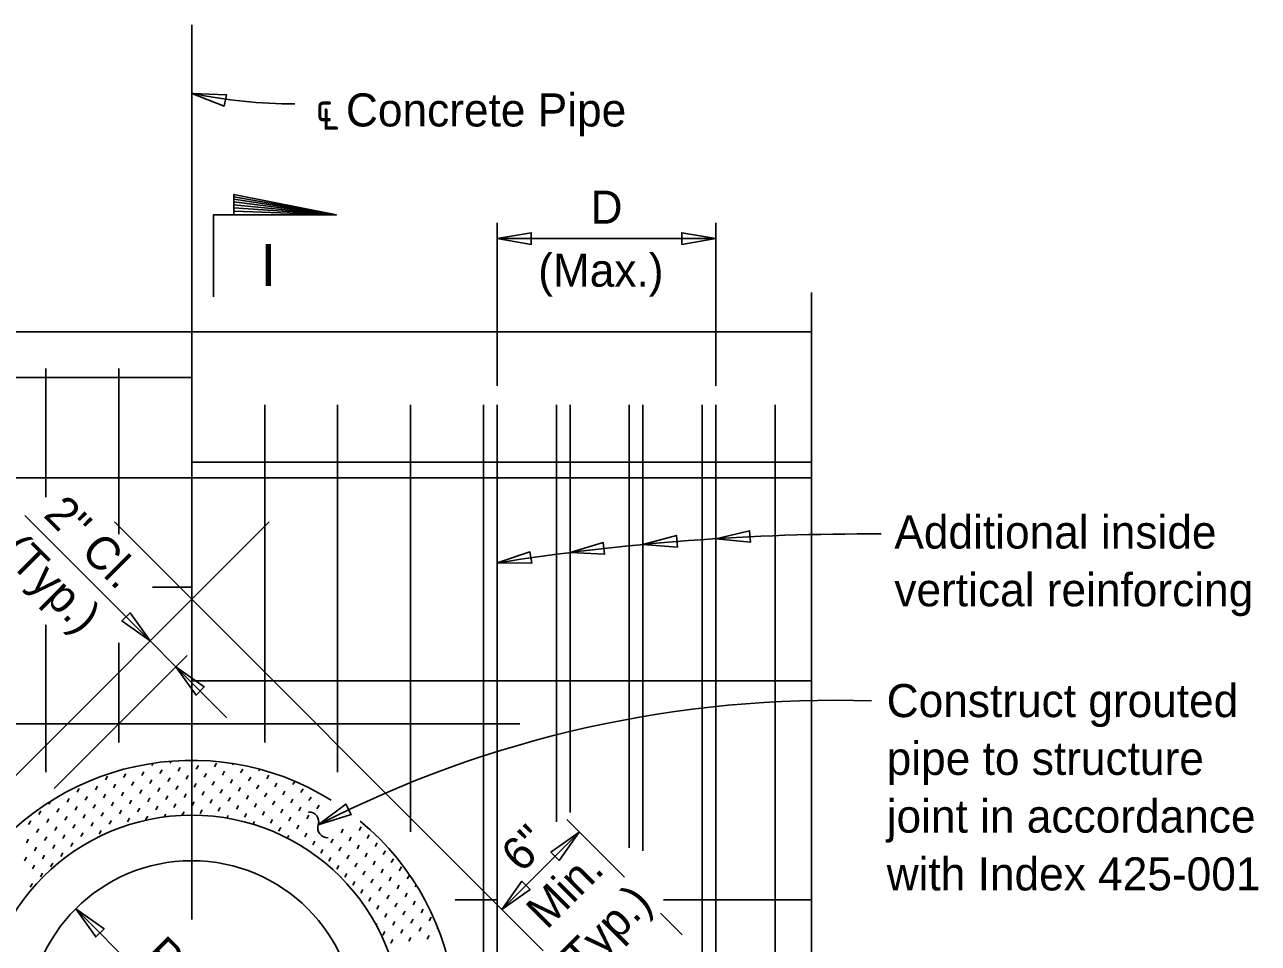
# Model space of a CAD drawing. Extents: x 10605.2 to 10672.7, y 76423.8 to 76450.2.
# Drawn here: x 10643.8 to 10649.44, y 76434.62 to 76438.82 of the extents above; entities that cross this region are included whole.
import ezdxf

# ---------------------------------------------------------------- set-up
doc = ezdxf.new("R2010")
doc.units = 0
for name, color, linetype in [('AdhocPoint_dp', 7, 'Continuous'), ('Border', 7, 'Continuous'), ('Patterning', 7, 'Continuous'), ('PlotBorder_dp', 7, 'Continuous'), ('SheetBorder_dp', 7, 'Continuous'), ('SheetLines_dp', 7, 'Continuous'), ('TextMisc', 7, 'Continuous')]:
    doc.layers.add(name, color=color, linetype=linetype)

msp = doc.modelspace()

# ---------------------------------------------------------------- linework, layer by layer
at = {"layer": 'AdhocPoint_dp'}
for p, q in [((10645.2285, 76437.947), (10644.7597, 76438.0295)), ((10644.7597, 76438.0195), (10645.2285, 76437.947)), ((10645.2285, 76437.947), (10644.7597, 76438.007)), ((10644.7597, 76437.9932), (10645.2285, 76437.947)), ((10645.2285, 76437.947), (10644.7597, 76437.9795)), ((10644.7597, 76437.9645), (10645.2285, 76437.947)), ((10645.9629, 76437.1656), (10645.9629, 76437.9115)), ((10646.9628, 76437.1656), (10646.9628, 76437.9115)), ((10645.9629, 76437.8391), (10646.9628, 76437.8391)), ((10643.8042, 76436.5724), (10644.3769, 76435.9996)), ((10644.4948, 76435.8818), (10644.3769, 76435.9996)), ((10643.9382, 76435.3252), (10644.5463, 76435.9333)), ((10644.4948, 76435.8818), (10644.7281, 76435.6485)), ((10646.5446, 76434.9197), (10646.2811, 76435.1831)), ((10646.3381, 76435.1261), (10645.9846, 76434.7726)), ((10645.0945, 76433.7181), (10644.0369, 76434.7757)), ((10646.8084, 76434.6559), (10646.7092, 76434.7551))]:
    msp.add_line(p, q, dxfattribs=at)
for points in [[(10644.5672, 76438.5028), (10644.7146, 76438.4448), (10644.7255, 76438.4966)], [(10645.963, 76437.8391), (10646.1191, 76437.8126), (10646.1191, 76437.8655)], [(10646.9629, 76437.8391), (10646.8067, 76437.8655), (10646.8067, 76437.8126)], [(10646.6295, 76436.4407), (10646.7825, 76436.4818), (10646.7875, 76436.4291)], [(10646.9629, 76436.4671), (10647.117, 76436.5035), (10647.1204, 76436.4507)], [(10646.2962, 76436.4038), (10646.4479, 76436.4496), (10646.4545, 76436.3971)], [(10645.963, 76436.3564), (10646.1131, 76436.4069), (10646.1214, 76436.3547)], [(10644.377, 76435.9996), (10644.2852, 76436.1288), (10644.2478, 76436.0914)], [(10644.4948, 76435.8818), (10644.5866, 76435.7526), (10644.624, 76435.79)], [(10645.1449, 76435.1594), (10645.296, 76435.2071), (10645.2719, 76435.2542)], [(10646.3382, 76435.1261), (10646.209, 76435.0344), (10646.2464, 76434.9969)], [(10645.9846, 76434.7726), (10646.1137, 76434.8643), (10646.0763, 76434.9017)], [(10644.0369, 76434.7757), (10644.1286, 76434.6466), (10644.1661, 76434.684)]]:
    msp.add_lwpolyline(points, close=True, dxfattribs=at)
for points in [[(10644.666, 76437.572), (10644.666, 76437.947), (10645.2285, 76437.947), (10644.7597, 76438.0407), (10644.7597, 76437.947)], [(10647.4003, 76430.898), (10647.4003, 76434.2116), (10647.3228, 76434.2116), (10647.4003, 76434.2454), (10647.4778, 76434.2791), (10647.4003, 76434.2791), (10647.4003, 76437.5929)]]:
    msp.add_lwpolyline(points, dxfattribs=at)
for centre, radius, start, end in [((10645.0309, 76440.7115), 2.2568, 258.1436, 270.1956), ((10647.6504, 76425.6856), 10.8034, 89.64038, 98.98612), ((10647.5038, 76430.5561), 5.1725, 88.1103, 117.1325), ((10645.1029, 76435.1732), 0.0447, 341.3118, 93.039), ((10645.1876, 76435.1446), 0.0447, 161.3118, 273.039)]:
    msp.add_arc(centre, radius, start, end, dxfattribs=at)
at = {"layer": 'Border'}
msp.add_line((10644.5672, 76438.8167), (10644.5672, 76434.7265), dxfattribs=at)
at = {"layer": 'Patterning'}
for p, q in [((10641.7341, 76437.2036), (10644.5672, 76437.2036)), ((10643.9006, 76437.2453), (10643.9006, 76436.657)), ((10644.2339, 76437.2453), (10644.2339, 76436.4885)), ((10644.5672, 76437.2453), (10644.5672, 76435.9075)), ((10644.9005, 76437.0787), (10644.9005, 76435.5363)), ((10645.2338, 76437.0787), (10645.2338, 76435.4)), ((10645.5671, 76437.0787), (10645.5671, 76435.1272)), ((10645.9004, 76437.0787), (10645.9004, 76431.4121)), ((10645.9629, 76437.0787), (10645.9629, 76431.4121)), ((10646.2337, 76437.0787), (10646.2337, 76435.1732)), ((10646.2962, 76437.0787), (10646.2962, 76435.2162)), ((10646.567, 76437.0787), (10646.567, 76435.0538)), ((10646.6295, 76437.0787), (10646.6295, 76435.0398)), ((10646.9003, 76437.0787), (10646.9003, 76431.4121)), ((10646.9628, 76437.0787), (10646.9628, 76431.4121)), ((10647.2336, 76437.0787), (10647.2336, 76431.4121)), ((10644.5672, 76436.817), (10647.4003, 76436.817)), ((10644.9208, 76436.5435), (10642.2691, 76433.8918)), ((10644.2137, 76436.5435), (10646.1735, 76434.5837)), ((10644.3874, 76436.2453), (10644.5672, 76436.2453)), ((10643.9006, 76436.0738), (10643.9006, 76435.4)), ((10644.2339, 76435.9918), (10644.2339, 76435.5363)), ((10644.5672, 76435.817), (10647.4003, 76435.817)), ((10644.5672, 76435.7102), (10644.5672, 76435.5786)), ((10643.0672, 76435.6204), (10646.0672, 76435.6204)), ((10645.7717, 76434.817), (10645.9629, 76434.817)), ((10646.7228, 76434.817), (10647.4003, 76434.817))]:
    msp.add_line(p, q, dxfattribs=at)
at = {"layer": 'PlotBorder_dp'}
msp.add_line((10641.7341, 76437.412), (10647.4003, 76437.412), dxfattribs=at)
msp.add_circle((10644.5672, 76434.2454), 0.75, dxfattribs=at)
msp.add_arc((10644.5672, 76434.2454), 1.2083, 58.2129, 50.3979, dxfattribs=at)
at = {"layer": 'SheetLines_dp'}
for p, q in [((10644.5512, 76435.4505), (10644.553, 76435.4536)), ((10644.3023, 76435.4214), (10644.3041, 76435.4246)), ((10644.3389, 76435.3847), (10644.3486, 76435.4015)), ((10644.3852, 76435.4311), (10644.3907, 76435.4406)), ((10644.4219, 76435.3945), (10644.4316, 76435.4113)), ((10644.4682, 76435.4408), (10644.4735, 76435.4499)), ((10644.5049, 76435.4042), (10644.5146, 76435.421)), ((10644.5878, 76435.4139), (10644.5976, 76435.4307)), ((10644.6708, 76435.4236), (10644.6805, 76435.4404)), ((10644.7074, 76435.387), (10644.7172, 76435.4038)), ((10644.7538, 76435.4333), (10644.7569, 76435.4386)), ((10644.7904, 76435.3967), (10644.8001, 76435.4135)), ((10644.8734, 76435.4064), (10644.8773, 76435.4131)), ((10644.1729, 76435.3653), (10644.1827, 76435.3821)), ((10644.2096, 76435.3287), (10644.2193, 76435.3455)), ((10644.2559, 76435.375), (10644.2656, 76435.3918)), ((10644.2925, 76435.3384), (10644.3023, 76435.3552)), ((10644.3755, 76435.3481), (10644.3852, 76435.3649)), ((10644.4585, 76435.3578), (10644.4682, 76435.3746)), ((10644.4951, 76435.3212), (10644.5049, 76435.338)), ((10644.5415, 76435.3676), (10644.5512, 76435.3843)), ((10644.5781, 76435.3309), (10644.5878, 76435.3477)), ((10644.6245, 76435.3773), (10644.6342, 76435.3941)), ((10644.6611, 76435.3406), (10644.6708, 76435.3574)), ((10644.7441, 76435.3504), (10644.7538, 76435.3672)), ((10644.827, 76435.3601), (10644.8368, 76435.3769)), ((10644.8637, 76435.3235), (10644.8734, 76435.3403)), ((10644.91, 76435.3698), (10644.9197, 76435.3866)), ((10644.9467, 76435.3332), (10644.9564, 76435.35)), ((10645.0296, 76435.3429), (10645.0383, 76435.3579)), ((10644.0436, 76435.3092), (10644.0533, 76435.326)), ((10644.0802, 76435.2726), (10644.09, 76435.2894)), ((10644.1266, 76435.3189), (10644.1363, 76435.3357)), ((10644.1632, 76435.2823), (10644.1729, 76435.2991)), ((10644.2462, 76435.292), (10644.2559, 76435.3088)), ((10644.3292, 76435.3018), (10644.3389, 76435.3186)), ((10644.3658, 76435.2651), (10644.3755, 76435.2819)), ((10644.4121, 76435.3115), (10644.4219, 76435.3283)), ((10644.4488, 76435.2749), (10644.4585, 76435.2916)), ((10644.5318, 76435.2846), (10644.5415, 76435.3014)), ((10644.6147, 76435.2943), (10644.6245, 76435.3111)), ((10644.6977, 76435.304), (10644.7074, 76435.3208)), ((10644.7343, 76435.2674), (10644.7441, 76435.2842)), ((10644.7807, 76435.3137), (10644.7904, 76435.3305)), ((10644.8173, 76435.2771), (10644.827, 76435.2939)), ((10644.9003, 76435.2868), (10644.91, 76435.3036)), ((10644.9833, 76435.2966), (10644.993, 76435.3134)), ((10645.0663, 76435.3063), (10645.076, 76435.3231)), ((10645.1029, 76435.2697), (10645.1126, 76435.2864)), ((10645.1859, 76435.2794), (10645.1875, 76435.2822)), ((10643.9143, 76435.2531), (10643.9223, 76435.267)), ((10643.9509, 76435.2165), (10643.9606, 76435.2333)), ((10643.9973, 76435.2629), (10644.007, 76435.2797)), ((10644.0339, 76435.2262), (10644.0436, 76435.243)), ((10644.1169, 76435.236), (10644.1266, 76435.2528)), ((10644.1998, 76435.2457), (10644.2096, 76435.2625)), ((10644.2365, 76435.2091), (10644.2462, 76435.2258)), ((10644.2828, 76435.2554), (10644.2925, 76435.2722)), ((10644.3194, 76435.2188), (10644.3292, 76435.2356)), ((10644.4024, 76435.2285), (10644.4121, 76435.2453)), ((10644.4854, 76435.2382), (10644.4951, 76435.255)), ((10644.5684, 76435.2479), (10644.5781, 76435.2647)), ((10644.605, 76435.2113), (10644.6147, 76435.2281)), ((10644.6514, 76435.2577), (10644.6611, 76435.2745)), ((10644.688, 76435.221), (10644.6977, 76435.2378)), ((10644.771, 76435.2308), (10644.7807, 76435.2476)), ((10644.8539, 76435.2405), (10644.8637, 76435.2573)), ((10644.9369, 76435.2502), (10644.9467, 76435.267)), ((10644.9736, 76435.2136), (10644.9833, 76435.2304)), ((10645.0199, 76435.2599), (10645.0296, 76435.2767)), ((10645.0565, 76435.2233), (10645.0663, 76435.2401)), ((10645.1395, 76435.233), (10645.1492, 76435.2498)), ((10643.8216, 76435.1604), (10643.8313, 76435.1772)), ((10643.8679, 76435.2068), (10643.8776, 76435.2236)), ((10643.9046, 76435.1702), (10643.9143, 76435.187)), ((10643.9875, 76435.1799), (10643.9973, 76435.1967)), ((10644.0705, 76435.1896), (10644.0802, 76435.2064)), ((10644.1071, 76435.153), (10644.1169, 76435.1698)), ((10644.1535, 76435.1993), (10644.1632, 76435.2161)), ((10644.1901, 76435.1627), (10644.1998, 76435.1795)), ((10644.2731, 76435.1724), (10644.2828, 76435.1892)), ((10644.3561, 76435.1821), (10644.3658, 76435.1989)), ((10644.4404, 76435.1942), (10644.4488, 76435.2087)), ((10644.522, 76435.2016), (10644.5318, 76435.2184)), ((10644.7273, 76435.189), (10644.7343, 76435.2012)), ((10644.8076, 76435.1941), (10644.8173, 76435.2109)), ((10644.8464, 76435.1613), (10644.8539, 76435.1743)), ((10644.8906, 76435.2039), (10644.9003, 76435.2207)), ((10644.9272, 76435.1672), (10644.9369, 76435.184)), ((10645.0102, 76435.177), (10645.0199, 76435.1937)), ((10645.0932, 76435.1867), (10645.1029, 76435.2035)), ((10643.8582, 76435.1238), (10643.8679, 76435.1406)), ((10643.9412, 76435.1335), (10643.9509, 76435.1503)), ((10643.9778, 76435.0969), (10643.9875, 76435.1137)), ((10644.0242, 76435.1433), (10644.0339, 76435.1601)), ((10644.0608, 76435.1066), (10644.0705, 76435.1234)), ((10644.1438, 76435.1164), (10644.1535, 76435.1331)), ((10644.9638, 76435.1306), (10644.9736, 76435.1474)), ((10645.0468, 76435.1403), (10645.0565, 76435.1571)), ((10645.0834, 76435.1037), (10645.0932, 76435.1205)), ((10645.2494, 76435.1231), (10645.2591, 76435.1399)), ((10645.3324, 76435.1329), (10645.3421, 76435.1497)), ((10645.369, 76435.0962), (10645.3787, 76435.113)), ((10643.8119, 76435.0775), (10643.8216, 76435.0943)), ((10643.8485, 76435.0408), (10643.8582, 76435.0576)), ((10643.8948, 76435.0872), (10643.9046, 76435.104)), ((10643.9315, 76435.0506), (10643.9412, 76435.0674)), ((10644.0144, 76435.0603), (10644.0242, 76435.0771)), ((10644.1057, 76435.0843), (10644.1071, 76435.0868)), ((10645.0026, 76435.0976), (10645.0102, 76435.1108)), ((10645.1201, 76435.0671), (10645.1298, 76435.0839)), ((10645.203, 76435.0768), (10645.2128, 76435.0936)), ((10645.2397, 76435.0402), (10645.2494, 76435.057)), ((10645.286, 76435.0865), (10645.2958, 76435.1033)), ((10645.3227, 76435.0499), (10645.3324, 76435.0667)), ((10645.4056, 76435.0596), (10645.4154, 76435.0764)), ((10643.8021, 76434.9945), (10643.8119, 76435.0113)), ((10643.8851, 76435.0042), (10643.8948, 76435.021)), ((10643.9681, 76435.0139), (10643.9778, 76435.0307)), ((10645.1567, 76435.0304), (10645.1664, 76435.0472)), ((10645.1933, 76434.9938), (10645.203, 76435.0106)), ((10645.2763, 76435.0035), (10645.286, 76435.0203)), ((10645.3593, 76435.0133), (10645.369, 76435.0301)), ((10645.4423, 76435.023), (10645.452, 76435.0398)), ((10645.4789, 76434.9864), (10645.4886, 76435.0031)), ((10643.8388, 76434.9579), (10643.8485, 76434.9746)), ((10643.9217, 76434.9676), (10643.9315, 76434.9844)), ((10645.23, 76434.9572), (10645.2397, 76434.974)), ((10645.3129, 76434.9669), (10645.3227, 76434.9837)), ((10645.3496, 76434.9303), (10645.3593, 76434.9471)), ((10645.3959, 76434.9766), (10645.4056, 76434.9934)), ((10645.4325, 76434.94), (10645.4423, 76434.9568)), ((10645.5155, 76434.9497), (10645.5252, 76434.9665)), ((10643.829, 76434.8749), (10643.8388, 76434.8917)), ((10643.8754, 76434.9212), (10643.8851, 76434.938)), ((10645.2666, 76434.9206), (10645.2763, 76434.9373)), ((10645.3032, 76434.8839), (10645.3129, 76434.9007)), ((10645.3862, 76434.8937), (10645.3959, 76434.9104)), ((10645.4692, 76434.9034), (10645.4789, 76434.9202)), ((10645.5521, 76434.9131), (10645.5619, 76434.9299)), ((10645.3398, 76434.8473), (10645.3496, 76434.8641)), ((10645.4228, 76434.857), (10645.4325, 76434.8738)), ((10645.4594, 76434.8204), (10645.4692, 76434.8372)), ((10645.5058, 76434.8667), (10645.5155, 76434.8835)), ((10645.5424, 76434.8301), (10645.5521, 76434.8469)), ((10645.5888, 76434.8765), (10645.593, 76434.8837)), ((10645.3765, 76434.8107), (10645.3862, 76434.8275)), ((10645.4131, 76434.774), (10645.4228, 76434.7908)), ((10645.4961, 76434.7838), (10645.5058, 76434.8006)), ((10645.5791, 76434.7935), (10645.5888, 76434.8103)), ((10645.4497, 76434.7374), (10645.4594, 76434.7542)), ((10645.5327, 76434.7471), (10645.5424, 76434.7639)), ((10645.5693, 76434.7105), (10645.5791, 76434.7273)), ((10645.6157, 76434.7569), (10645.6254, 76434.7737)), ((10645.6523, 76434.7202), (10645.662, 76434.737)), ((10645.4091, 76434.701), (10645.4131, 76434.7079)), ((10645.44, 76434.6544), (10645.4497, 76434.6712)), ((10645.4864, 76434.7008), (10645.4961, 76434.7176)), ((10645.523, 76434.6642), (10645.5327, 76434.681)), ((10645.606, 76434.6739), (10645.6157, 76434.6907)), ((10645.6889, 76434.6836), (10645.6914, 76434.6879)), ((10645.4766, 76434.6178), (10645.4864, 76434.6346)), ((10645.5596, 76434.6275), (10645.5693, 76434.6443)), ((10645.6426, 76434.6373), (10645.6523, 76434.654))]:
    msp.add_line(p, q, dxfattribs=at)
at = {"layer": 'TextMisc'}
msp.add_line((10641.7341, 76436.7454), (10647.4003, 76436.7454), dxfattribs=at)
msp.add_circle((10644.5672, 76434.2454), 0.9583, dxfattribs=at)

# ---------------------------------------------------------------- texts
at = {"layer": 'AdhocPoint_dp'}
for s, rotation, p in [('2" Cl.', 315, (10643.8842, 76436.5713)), ('(Typ.)', 315, (10643.6843, 76436.3978)), ('6"', 45, (10646.0749, 76434.9354)), ('Min.', 45, (10646.1898, 76434.677)), ('(Typ.)', 45, (10646.3056, 76434.4194)), ('Pipe ID', 315, (10644.34, 76434.5558))]:
    msp.add_text(s, height=0.1512, rotation=rotation, dxfattribs=at).set_placement(p)
for s, p in [('Additional inside', (10647.7787, 76436.4221)), ('vertical reinforcing', (10647.7787, 76436.1581)), ('Construct grouted', (10647.7436, 76435.6515)), ('pipe to structure', (10647.7436, 76435.3875)), ('joint in accordance', (10647.7436, 76435.1235)), ('with Index 425-001', (10647.7436, 76434.8595))]:
    msp.add_text(s, height=0.1512, dxfattribs=at).set_placement(p)
at = {"layer": 'SheetBorder_dp'}
for s, height, p in [('℄ Concrete Pipe', 0.1512, (10645.1338, 76438.3514)), ('D', 0.1512, (10646.3901, 76437.907)), ('I', 0.192, (10644.882, 76437.6226)), ('(Max.)', 0.1512, (10646.1507, 76437.619))]:
    msp.add_text(s, height=height, dxfattribs=at).set_placement(p)

doc.saveas('drawing.dxf')
